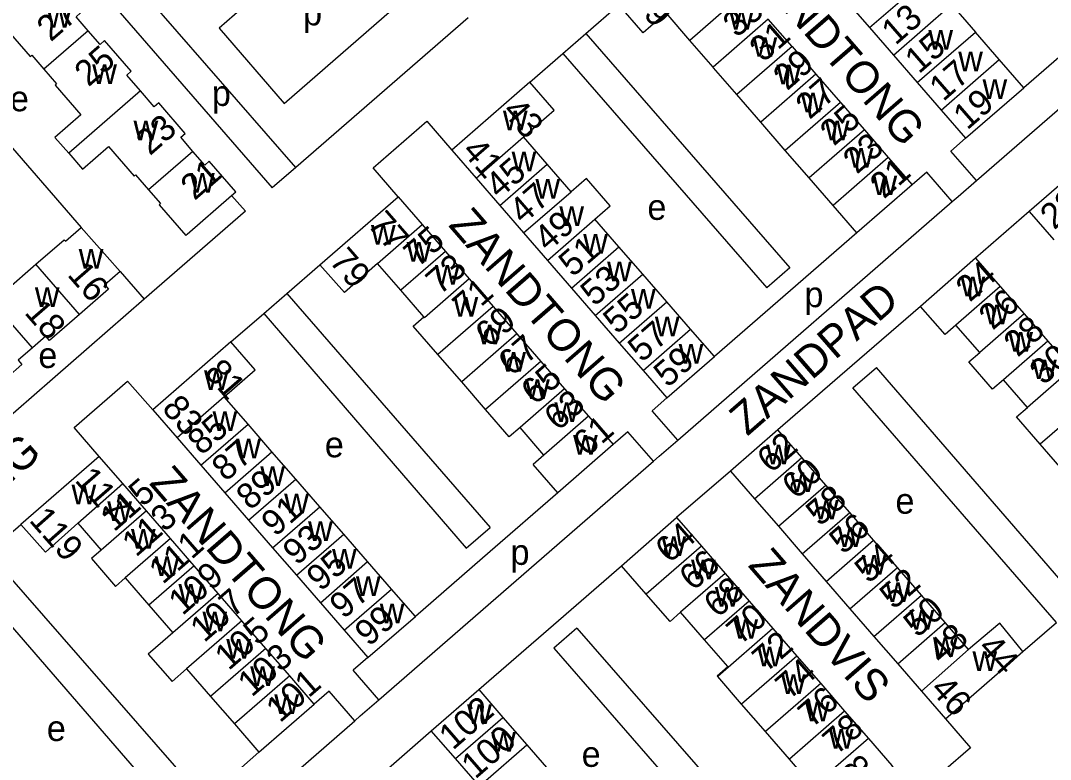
# Model space of a CAD drawing. Extents: x 155854 to 157362, y 383621 to 384685.
# Drawn here: x 156498.5 to 156659.8, y 384332.2 to 384447.9 of the extents above; entities that cross this region are included whole.
import ezdxf

# ---------------------------------------------------------------- set-up
doc = ezdxf.new("R2010")
doc.units = 0
for name, color, linetype in [('BLT_Basislijn', 7, 'Continuous'), ('BLT_Bebouwing', 7, 'Continuous'), ('BLT_Centroide', 7, 'Continuous'), ('BLT_Huisnummer', 7, 'Continuous'), ('BLT_Huisnummer_ tussenligend', 7, 'Continuous'), ('BLT_Huisnummer_reeks', 7, 'Continuous'), ('BLT_Onderverdeling_panden', 7, 'Continuous'), ('BLT_Straatnaam', 7, 'Continuous')]:
    doc.layers.add(name, color=color, linetype=linetype)

msp = doc.modelspace()

# ---------------------------------------------------------------- linework, layer by layer
at = {"layer": 'BLT_Basislijn'}
for p, q in [((156541.64, 384424.92), (156508.8, 384462.59)), ((156505.19, 384459.46), (156537.93, 384421.71)), ((156587.05, 384445.89), (156592.21, 384450.37)), ((156568.62, 384448.35), (156541.64, 384424.92)), ((156667.24, 384447.45), (156655.65, 384437.39)), ((156583.44, 384442.75), (156587.05, 384445.89)), ((156578.29, 384438.28), (156583.44, 384442.75)), ((156583.44, 384442.75), (156615.4, 384406.06)), ((156494.81, 384430.72), (156508, 384415.52)), ((156648.22, 384422.86), (156644.22, 384427.48)), ((156541.64, 384424.92), (156537.93, 384421.71)), ((156644.45, 384419.58), (156640.45, 384424.2)), ((156531.54, 384420.51), (156533.76, 384418.07)), ((156533.76, 384418.07), (156517.89, 384404.28)), ((156656.48, 384418.02), (156648.08, 384410.74)), ((156514.12, 384408.62), (156517.89, 384404.28)), ((156540.2, 384405.2), (156545.38, 384409.7)), ((156536.6, 384402.08), (156540.2, 384405.2)), ((156540.2, 384405.2), (156572.08, 384368.57)), ((156517.89, 384404.28), (156463.21, 384356.78)), ((156531.46, 384397.61), (156536.6, 384402.08)), ((156639.47, 384403.18), (156628.75, 384393.9)), ((156628.75, 384393.9), (156617.13, 384383.84)), ((156664.38, 384356.83), (156632.56, 384393.62)), ((156601.43, 384382.21), (156597.42, 384386.82)), ((156597.65, 384378.93), (156593.64, 384383.54)), ((156609.69, 384377.39), (156601.27, 384370.09)), ((156582.67, 384373.99), (156572.04, 384364.78)), ((156493.41, 384364.56), (156498.56, 384369.04)), ((156572.04, 384364.78), (156560.34, 384354.62)), ((156581.99, 384353.33), (156592.62, 384362.57)), ((156489.82, 384361.43), (156521.66, 384324.72)), ((156655.52, 384349.15), (156660.76, 384353.69)), ((156570.29, 384343.17), (156581.99, 384353.33)), ((156585.66, 384352.81), (156617.61, 384316.2)), ((156552.91, 384348.2), (156550.6, 384346.19)), ((156554.61, 384341.57), (156550.6, 384346.19)), ((156546.82, 384342.91), (156544.51, 384340.9)), ((156550.84, 384338.29), (156546.82, 384342.91)), ((156554.48, 384329.42), (156562.84, 384336.72)), ((156525.13, 384324.03), (156535.85, 384333.36))]:
    msp.add_line(p, q, dxfattribs=at)
for points in [[(156648.22, 384422.86), (156694.85, 384463.4), (156691.17, 384468.24)], [(156587.05, 384445.89), (156619, 384409.22), (156615.4, 384406.06)], [(156557.63, 384420.32), (156553.73, 384424.89), (156562.12, 384432.16), (156566.04, 384427.64)], [(156646.53, 384429.49), (156644.22, 384427.48)], [(156640.45, 384424.2), (156638.14, 384422.19)], [(156644.45, 384419.58), (156645.36, 384420.38), (156648.22, 384422.86)], [(156601.43, 384382.21), (156644.45, 384419.58)], [(156629.49, 384414.69), (156619.12, 384405.68)], [(156619.12, 384405.68), (156607.18, 384395.3)], [(156536.6, 384402.08), (156568.3, 384365.31), (156572.08, 384368.57)], [(156660.76, 384353.69), (156628.85, 384390.4), (156632.56, 384393.62)], [(156510.82, 384379.68), (156506.9, 384384.19), (156515.28, 384391.46), (156519.21, 384386.97)], [(156599.74, 384388.83), (156597.42, 384386.82)], [(156593.64, 384383.54), (156591.32, 384381.53)], [(156597.65, 384378.93), (156598.54, 384379.7), (156601.43, 384382.21)], [(156554.61, 384341.57), (156597.65, 384378.93)], [(156493.41, 384364.56), (156525.42, 384328), (156521.66, 384324.72)], [(156585.66, 384352.81), (156582.05, 384349.68), (156613.96, 384313.03)], [(156550.84, 384338.29), (156551.69, 384339.04), (156554.61, 384341.57)], [(156510.15, 384302.85), (156550.84, 384338.29)], [(156643.36, 384338.6), (156647.29, 384334.04), (156638.86, 384326.74), (156634.97, 384331.3)]]:
    msp.add_lwpolyline(points, dxfattribs=at)
msp.add_lwpolyline([(156539.82, 384434.95), (156559.04, 384451.74), (156548.85, 384463.47), (156529.59, 384446.72)], close=True, dxfattribs=at)
at = {"layer": 'BLT_Bebouwing'}
for p, q in [((156644.32, 384450.43), (156648.06, 384446.12)), ((156619.35, 384443.86), (156615.62, 384448.16)), ((156619.35, 384443.86), (156623.09, 384439.54)), ((156623.09, 384439.54), (156626.93, 384435.11)), ((156578.29, 384438.28), (156566.04, 384427.64)), ((156626.93, 384435.11), (156630.67, 384430.8)), ((156630.67, 384430.8), (156634.42, 384426.49)), ((156566.04, 384427.64), (156569.85, 384423.25)), ((156634.42, 384426.49), (156638.14, 384422.19)), ((156663.92, 384424.49), (156656.48, 384418.02)), ((156569.85, 384423.25), (156573.56, 384418.98)), ((156545.38, 384409.7), (156557.63, 384420.32)), ((156557.63, 384420.32), (156561.4, 384415.98)), ((156573.56, 384418.98), (156577.3, 384414.67)), ((156508, 384415.52), (156514.12, 384408.62)), ((156561.4, 384415.98), (156565.05, 384411.77)), ((156577.3, 384414.67), (156581.05, 384410.36)), ((156565.05, 384411.77), (156568.79, 384407.48)), ((156558.06, 384405.7), (156554.4, 384409.91)), ((156581.05, 384410.36), (156584.79, 384406.05)), ((156648.08, 384410.74), (156639.47, 384403.18)), ((156648.08, 384410.74), (156651.97, 384406.27)), ((156568.79, 384407.48), (156572.53, 384403.17)), ((156584.79, 384406.05), (156588.53, 384401.74)), ((156651.97, 384406.27), (156655.68, 384401.99)), ((156572.53, 384403.17), (156576.26, 384398.87)), ((156655.68, 384401.99), (156659.4, 384397.71)), ((156588.53, 384401.74), (156592.27, 384397.43)), ((156648.74, 384395.96), (156645.02, 384400.24)), ((156576.26, 384398.87), (156580, 384394.56)), ((156531.46, 384397.61), (156519.21, 384386.97)), ((156592.27, 384397.43), (156596.01, 384393.13)), ((156659.4, 384397.71), (156663.17, 384393.38)), ((156580, 384394.56), (156583.73, 384390.27)), ((156599.74, 384388.83), (156607.18, 384395.3)), ((156596.01, 384393.13), (156599.74, 384388.83)), ((156656.22, 384387.34), (156652.46, 384391.67)), ((156583.73, 384390.27), (156587.47, 384385.97)), ((156519.21, 384386.97), (156523.02, 384382.59)), ((156587.47, 384385.97), (156591.32, 384381.53)), ((156576.74, 384384.2), (156575.06, 384382.74)), ((156523.02, 384382.59), (156526.74, 384378.31)), ((156617.13, 384383.84), (156609.69, 384377.39)), ((156510.82, 384379.68), (156498.56, 384369.04)), ((156514.51, 384375.44), (156510.82, 384379.68)), ((156580.48, 384379.9), (156578.8, 384378.44)), ((156526.74, 384378.31), (156530.49, 384374)), ((156609.69, 384377.39), (156613.46, 384373.05)), ((156518.23, 384371.15), (156514.51, 384375.44)), ((156530.49, 384374), (156534.23, 384369.69)), ((156613.46, 384373.05), (156617.2, 384368.74)), ((156521.99, 384366.82), (156518.23, 384371.15)), ((156534.23, 384369.69), (156537.97, 384365.39)), ((156507.49, 384369.21), (156511.15, 384364.99)), ((156617.2, 384368.74), (156620.94, 384364.43)), ((156525.7, 384362.55), (156521.99, 384366.82)), ((156537.97, 384365.39), (156541.72, 384361.07)), ((156620.94, 384364.43), (156624.68, 384360.12)), ((156529.46, 384358.22), (156525.7, 384362.55)), ((156514.91, 384360.67), (156518.62, 384356.4)), ((156541.72, 384361.07), (156545.46, 384356.77)), ((156624.68, 384360.12), (156628.42, 384355.81)), ((156533.18, 384353.93), (156529.46, 384358.22)), ((156545.46, 384356.77), (156549.2, 384352.46)), ((156518.62, 384356.4), (156522.38, 384352.07)), ((156628.42, 384355.81), (156632.17, 384351.5)), ((156536.94, 384349.61), (156533.18, 384353.93)), ((156549.2, 384352.46), (156552.91, 384348.2)), ((156632.17, 384351.5), (156635.9, 384347.19)), ((156540.67, 384345.32), (156536.94, 384349.61)), ((156643.36, 384338.6), (156655.52, 384349.15)), ((156635.9, 384347.19), (156639.62, 384342.9)), ((156544.51, 384340.9), (156540.67, 384345.32)), ((156639.62, 384342.9), (156643.36, 384338.6)), ((156618.93, 384332.28), (156615.18, 384336.61))]:
    msp.add_line(p, q, dxfattribs=at)
for points in [[(156509.11, 384446.34), (156507.2, 384448.53), (156507.88, 384449.12), (156503.74, 384453.9), (156503.07, 384453.3)], [(156599.61, 384449.12), (156596.01, 384445.99), (156592.21, 384450.37)], [(156627.74, 384451.12), (156631.48, 384446.82)], [(156603.33, 384444.83), (156599.61, 384449.12)], [(156490.46, 384446.71), (156492.62, 384444.23), (156495.89, 384447.07), (156500.03, 384442.3), (156500.25, 384442.5), (156502.16, 384440.3)], [(156515.14, 384439.39), (156515.82, 384439.99), (156511.67, 384444.78), (156510.99, 384444.16), (156509.11, 384446.34)], [(156631.48, 384446.82), (156635.22, 384442.52)], [(156651.81, 384441.81), (156648.06, 384446.12)], [(156606.97, 384440.64), (156603.33, 384444.83)], [(156635.22, 384442.52), (156638.96, 384438.21)], [(156610.7, 384436.34), (156607.05, 384440.55), (156606.97, 384440.64)], [(156655.65, 384437.39), (156651.81, 384441.81)], [(156502.16, 384440.3), (156504.16, 384438), (156503.94, 384437.8), (156507.97, 384433.16)], [(156517.29, 384436.91), (156515.14, 384439.39)], [(156577.28, 384429.72), (156582.1, 384433.9), (156578.29, 384438.28)], [(156638.96, 384438.21), (156642.7, 384433.9)], [(156646.53, 384429.49), (156655.65, 384437.39)], [(156525.51, 384427.45), (156523.6, 384429.65), (156524.29, 384430.22), (156520.15, 384435.03), (156519.44, 384434.43), (156517.29, 384436.91)], [(156614.44, 384432.03), (156610.7, 384436.34)], [(156507.97, 384433.16), (156503.89, 384429.62), (156506.04, 384427.14)], [(156642.7, 384433.9), (156646.53, 384429.49)], [(156618.29, 384427.6), (156614.44, 384432.03)], [(156581, 384425.44), (156577.28, 384429.72)], [(156506.04, 384427.14), (156508.19, 384424.66), (156512.27, 384428.19)], [(156512.27, 384428.19), (156516.29, 384423.57), (156516.52, 384423.76), (156518.56, 384421.42)], [(156531.54, 384420.51), (156532.21, 384421.11), (156528.07, 384425.89), (156527.38, 384425.29), (156525.51, 384427.45)], [(156622.03, 384423.29), (156618.29, 384427.6)], [(156584.74, 384421.13), (156581, 384425.44)], [(156588.48, 384416.82), (156590.87, 384418.9), (156587.13, 384423.21), (156584.74, 384421.13)], [(156625.77, 384418.98), (156622.03, 384423.29)], [(156518.56, 384421.42), (156520.42, 384419.28), (156520.2, 384419.08), (156524.37, 384414.28), (156524.6, 384414.48), (156531.54, 384420.51)], [(156638.14, 384422.19), (156629.49, 384414.69)], [(156629.49, 384414.69), (156625.77, 384418.98)], [(156656.48, 384418.02), (156660.35, 384413.57)], [(156592.22, 384412.51), (156588.48, 384416.82)], [(156500.92, 384409.77), (156505.33, 384413.6), (156505.53, 384413.37), (156508, 384415.52)], [(156595.97, 384408.2), (156592.22, 384412.51)], [(156554.4, 384409.91), (156549.23, 384405.36), (156545.38, 384409.7)], [(156494.34, 384403.62), (156496.43, 384405.47), (156496.23, 384405.69), (156500.92, 384409.77)], [(156514.12, 384408.62), (156511.69, 384406.54), (156512.3, 384405.86), (156507.75, 384401.91)], [(156599.71, 384403.9), (156595.97, 384408.2)], [(156561.66, 384401.56), (156558.06, 384405.7)], [(156603.45, 384399.59), (156599.71, 384403.9)], [(156507.75, 384401.91), (156503.05, 384397.83), (156502.46, 384398.52), (156500.37, 384396.68)], [(156645.02, 384400.24), (156643.32, 384398.75), (156639.47, 384403.18)], [(156563.86, 384395.64), (156559.99, 384400.1), (156561.66, 384401.56)], [(156607.18, 384395.3), (156603.45, 384399.59)], [(156530.4, 384389), (156535.27, 384393.22), (156531.46, 384397.61)], [(156500.37, 384396.68), (156498.11, 384394.74), (156498.71, 384394.06), (156494.16, 384390.1)], [(156567.6, 384391.34), (156563.86, 384395.64)], [(156652.46, 384391.67), (156650.75, 384390.19), (156647.03, 384394.48), (156648.74, 384395.96)], [(156571.34, 384387.03), (156567.6, 384391.34)], [(156534.13, 384384.72), (156530.4, 384389)], [(156658.22, 384381.59), (156654.52, 384385.86), (156656.22, 384387.34)], [(156575.06, 384382.74), (156571.34, 384387.03)], [(156537.88, 384380.42), (156534.13, 384384.72)], [(156580.48, 384379.9), (156576.74, 384384.2)], [(156620.89, 384379.51), (156617.13, 384383.84)], [(156591.32, 384381.53), (156582.67, 384373.99)], [(156661.96, 384377.29), (156658.22, 384381.59)], [(156541.62, 384376.11), (156537.88, 384380.42)], [(156624.63, 384375.2), (156620.89, 384379.51)], [(156582.67, 384373.99), (156578.8, 384378.44)], [(156545.37, 384371.81), (156541.62, 384376.11)], [(156628.38, 384370.89), (156624.63, 384375.2)], [(156549.12, 384367.51), (156545.37, 384371.81)], [(156592.62, 384362.57), (156601.27, 384370.09)], [(156601.27, 384370.09), (156605.15, 384365.62)], [(156632.12, 384366.58), (156628.38, 384370.89)], [(156498.56, 384369.04), (156502.4, 384364.7), (156507.49, 384369.21)], [(156552.87, 384363.2), (156549.12, 384367.51)], [(156635.86, 384362.27), (156632.12, 384366.58)], [(156511.15, 384364.99), (156509.62, 384363.67), (156513.36, 384359.33), (156514.91, 384360.67)], [(156605.15, 384365.62), (156608.87, 384361.35)], [(156556.61, 384358.9), (156552.87, 384363.2)], [(156596.5, 384358.11), (156592.62, 384362.57)], [(156639.6, 384357.96), (156635.86, 384362.27)], [(156608.87, 384361.35), (156612.62, 384357.02)], [(156560.34, 384354.62), (156556.61, 384358.9)], [(156601.88, 384355.28), (156600.23, 384353.82), (156596.5, 384358.11)], [(156612.62, 384357.02), (156616.36, 384352.72)], [(156643.34, 384353.65), (156639.6, 384357.96)], [(156605.64, 384350.95), (156601.88, 384355.28)], [(156552.91, 384348.2), (156560.34, 384354.62)], [(156647, 384349.43), (156643.34, 384353.65)], [(156655.52, 384349.15), (156651.89, 384353.56), (156647, 384349.43)], [(156522.38, 384352.07), (156520.79, 384350.69), (156518.51, 384348.73), (156522.24, 384344.43), (156524.52, 384346.41)], [(156616.36, 384352.72), (156620.09, 384348.42)], [(156609.27, 384346.78), (156605.64, 384350.95)], [(156620.09, 384348.42), (156623.83, 384344.12)], [(156524.52, 384346.41), (156528.27, 384342.09)], [(156607.6, 384345.33), (156609.27, 384346.78)], [(156607.7, 384345.21), (156607.6, 384345.33)], [(156611.44, 384340.9), (156607.7, 384345.21)], [(156623.83, 384344.12), (156627.58, 384339.8)], [(156562.84, 384336.72), (156570.29, 384343.17)], [(156570.29, 384343.17), (156574.07, 384338.82)], [(156528.27, 384342.09), (156532, 384337.79)], [(156535.85, 384333.36), (156544.51, 384340.9)], [(156615.18, 384336.61), (156611.44, 384340.9)], [(156627.58, 384339.8), (156631.3, 384335.52)], [(156532, 384337.79), (156535.85, 384333.36)], [(156574.07, 384338.82), (156577.81, 384334.52)], [(156566.63, 384332.36), (156562.84, 384336.72)], [(156577.81, 384334.52), (156581.55, 384330.21)], [(156631.3, 384335.52), (156634.97, 384331.3)], [(156570.37, 384328.06), (156566.63, 384332.36)], [(156622.52, 384328.15), (156618.93, 384332.28)]]:
    msp.add_lwpolyline(points, dxfattribs=at)
at = {"layer": 'BLT_Onderverdeling_panden'}
for p, q in [((156631.48, 384446.82), (156640.59, 384454.73)), ((156611.99, 384452.35), (156603.33, 384444.83)), ((156635.22, 384442.52), (156644.32, 384450.43)), ((156615.62, 384448.16), (156606.97, 384440.64)), ((156509.11, 384446.34), (156502.16, 384440.3)), ((156638.96, 384438.21), (156648.06, 384446.12)), ((156619.35, 384443.86), (156610.7, 384436.34)), ((156642.7, 384433.9), (156651.81, 384441.81)), ((156623.09, 384439.54), (156614.44, 384432.03)), ((156517.29, 384436.91), (156506.04, 384427.14)), ((156626.93, 384435.11), (156618.29, 384427.6)), ((156569.85, 384423.25), (156577.28, 384429.72)), ((156630.67, 384430.8), (156622.03, 384423.29)), ((156525.51, 384427.45), (156518.56, 384421.42)), ((156634.42, 384426.49), (156625.77, 384418.98)), ((156573.56, 384418.98), (156581, 384425.44)), ((156577.3, 384414.67), (156584.74, 384421.13)), ((156581.05, 384410.36), (156588.48, 384416.82)), ((156554.4, 384409.91), (156561.4, 384415.98)), ((156565.05, 384411.77), (156558.06, 384405.7)), ((156584.79, 384406.05), (156592.22, 384412.51)), ((156507.75, 384401.91), (156500.92, 384409.77)), ((156588.53, 384401.74), (156595.97, 384408.2)), ((156651.97, 384406.27), (156645.02, 384400.24)), ((156500.37, 384396.68), (156494.34, 384403.62)), ((156592.27, 384397.43), (156599.71, 384403.9)), ((156572.53, 384403.17), (156563.86, 384395.64)), ((156655.68, 384401.99), (156648.74, 384395.96)), ((156576.26, 384398.87), (156567.6, 384391.34)), ((156596.01, 384393.13), (156603.45, 384399.59)), ((156659.4, 384397.71), (156652.46, 384391.67)), ((156580, 384394.56), (156571.34, 384387.03)), ((156663.17, 384393.38), (156656.22, 384387.34)), ((156530.4, 384389), (156523.02, 384382.59)), ((156583.73, 384390.27), (156576.74, 384384.2)), ((156666.88, 384389.11), (156658.22, 384381.59)), ((156587.47, 384385.97), (156580.48, 384379.9)), ((156526.74, 384378.31), (156534.13, 384384.72)), ((156530.49, 384374), (156537.88, 384380.42)), ((156613.46, 384373.05), (156620.89, 384379.51)), ((156534.23, 384369.69), (156541.62, 384376.11)), ((156507.49, 384369.21), (156514.51, 384375.44)), ((156617.2, 384368.74), (156624.63, 384375.2)), ((156537.97, 384365.39), (156545.37, 384371.81)), ((156518.23, 384371.15), (156511.15, 384364.99)), ((156620.94, 384364.43), (156628.38, 384370.89)), ((156521.99, 384366.82), (156514.91, 384360.67)), ((156541.72, 384361.07), (156549.12, 384367.51)), ((156624.68, 384360.12), (156632.12, 384366.58)), ((156605.15, 384365.62), (156596.5, 384358.11)), ((156545.46, 384356.77), (156552.87, 384363.2)), ((156525.7, 384362.55), (156518.62, 384356.4)), ((156628.42, 384355.81), (156635.86, 384362.27)), ((156608.87, 384361.35), (156601.88, 384355.28)), ((156549.2, 384352.46), (156556.61, 384358.9)), ((156612.62, 384357.02), (156605.64, 384350.95)), ((156632.17, 384351.5), (156639.6, 384357.96)), ((156533.18, 384353.93), (156524.52, 384346.41)), ((156635.9, 384347.19), (156643.34, 384353.65)), ((156616.36, 384352.72), (156607.7, 384345.21)), ((156536.94, 384349.61), (156528.27, 384342.09)), ((156647, 384349.43), (156639.62, 384342.9)), ((156620.09, 384348.42), (156611.44, 384340.9)), ((156540.67, 384345.32), (156532, 384337.79)), ((156623.83, 384344.12), (156615.18, 384336.61)), ((156627.58, 384339.8), (156618.93, 384332.28)), ((156566.63, 384332.36), (156574.07, 384338.82)), ((156570.37, 384328.06), (156577.81, 384334.52))]:
    msp.add_line(p, q, dxfattribs=at)
for points in [[(156568.79, 384407.48), (156561.8, 384401.4), (156561.66, 384401.56)], [(156529.46, 384358.22), (156522.38, 384352.07)], [(156631.3, 384335.52), (156622.65, 384328), (156622.52, 384328.15)]]:
    msp.add_lwpolyline(points, dxfattribs=at)

# ---------------------------------------------------------------- texts
at = {"layer": 'BLT_Centroide'}
for s, p in [('p', (156542.76, 384447.18)), ('w', (156502.61, 384446.8)), ('w', (156609.48, 384446.5)), ('w', (156640.7, 384443.37)), ('w', (156613.16, 384442.25)), ('w', (156645.38, 384440)), ('w', (156509.73, 384437.98)), ('w', (156616.9, 384437.94)), ('p', (156528.47, 384434.56)), ('w', (156649.18, 384435.66)), ('e', (156496.83, 384433.72)), ('w', (156620.69, 384433.56)), ('w', (156574.06, 384430.75)), ('w', (156516.2, 384429.16)), ('w', (156624.48, 384429.19)), ('w', (156628.23, 384424.91)), ('w', (156575.42, 384424.34)), ('w', (156525.05, 384420.97)), ('w', (156579.15, 384420.06)), ('w', (156631.96, 384420.59)), ('e', (156596.69, 384416.72)), ('w', (156582.9, 384415.75)), ('w', (156553.39, 384412.84)), ('w', (156558.97, 384410.19)), ('w', (156586.63, 384411.44)), ('w', (156507.62, 384409.08)), ('w', (156590.38, 384407.12)), ('w', (156563.42, 384406.59)), ('w', (156645.73, 384404.75)), ('w', (156500.75, 384403.09)), ('w', (156594.12, 384402.81)), ('p', (156621.29, 384403.05)), ('w', (156566.32, 384401.56)), ('w', (156649.49, 384400.38)), ('w', (156570.06, 384397.25)), ('w', (156597.86, 384398.5)), ('w', (156653.22, 384396.09)), ('w', (156601.59, 384394.22)), ('e', (156501.29, 384393.53)), ('w', (156573.8, 384392.94)), ('w', (156656.95, 384391.78)), ('w', (156527.24, 384390.09)), ('w', (156577.53, 384388.66)), ('w', (156582.11, 384385.09)), ('w', (156528.58, 384383.66)), ('w', (156532.3, 384379.38)), ('e', (156546.16, 384379.54)), ('w', (156585.05, 384379.97)), ('w', (156615.29, 384378.44)), ('w', (156536.05, 384375.06)), ('w', (156619.04, 384374.12)), ('w', (156506.49, 384372.19)), ('w', (156539.8, 384370.75)), ('w', (156622.79, 384369.81)), ('e', (156635.54, 384370.71)), ('w', (156512.09, 384369.56)), ('w', (156515.8, 384365.25)), ('w', (156543.54, 384366.44)), ('w', (156626.52, 384365.5)), ('w', (156598.89, 384364.09)), ('w', (156547.29, 384362.12)), ('p', (156575.25, 384362.7)), ('w', (156519.52, 384360.94)), ('w', (156603.52, 384360.44)), ('w', (156630.27, 384361.19)), ('w', (156551.03, 384357.84)), ('w', (156634.01, 384356.88)), ('w', (156523.24, 384356.62)), ('w', (156607.25, 384356.16)), ('w', (156526.99, 384352.31)), ('w', (156554.77, 384353.56)), ('w', (156637.75, 384352.56)), ('w', (156610.16, 384351.12)), ('w', (156530.73, 384348)), ('w', (156641.42, 384348.28)), ('w', (156613.9, 384346.81)), ('w', (156647.6, 384346.09)), ('w', (156534.48, 384343.72)), ('w', (156617.63, 384342.5)), ('w', (156538.25, 384339.34)), ('w', (156568.45, 384337.78)), ('w', (156621.38, 384338.19)), ('e', (156502.62, 384335.12)), ('w', (156572.22, 384333.44)), ('w', (156625.12, 384333.91)), ('e', (156586.39, 384331.07))]:
    msp.add_text(s, height=4, dxfattribs=at).set_placement(p)
at = {"layer": 'BLT_Huisnummer'}
for s, rotation, p in [('27', 40.9815, (156503.23, 384444.49)), ('33', 40.9795, (156610.7, 384445.12)), ('15', 40.9786, (156639.21, 384439.47)), ('25', 40.9815, (156509.14, 384437.44)), ('29', 40.9795, (156618.57, 384436.85)), ('19', 40.9786, (156646.78, 384430.68)), ('25', 40.9795, (156625.9, 384428.17)), ('23', 40.9815, (156518.76, 384426.67)), ('21', 40.9795, (156633.73, 384419.89)), ('21', 40.9815, (156525.76, 384419.65)), ('47', 40.9795, (156577.22, 384415.91)), ('22', 41.2107, (156660.41, 384415.05)), ('51', 40.9795, (156584.98, 384407.64)), ('16', 310.985, (156505.7, 384408.07)), ('73', 40.9795, (156564.18, 384404.84)), ('24', 40.9816, (156647.18, 384403.74)), ('55', 40.9795, (156591.95, 384398.68)), ('69', 40.9795, (156571.9, 384396.58)), ('28', 40.9816, (156654.68, 384395.11)), ('59', 40.9795, (156599.86, 384390.33)), ('65', 40.9795, (156579.09, 384387.6)), ('61', 40.9795, (156587.25, 384379.52)), ('62', 40.9799, (156616.05, 384376.92)), ('87', 40.9795, (156530.64, 384375.61)), ('58', 40.9799, (156623.7, 384368.61)), ('91', 40.9795, (156538.4, 384366.98)), ('113', 40.9795, (156516.58, 384363.81)), ('64', 40.9816, (156600.11, 384362.83)), ('95', 40.9795, (156545.49, 384358.42)), ('54', 40.9799, (156631.34, 384359.65)), ('109', 40.9795, (156523.86, 384354.65)), ('68', 40.9816, (156607.7, 384354.28)), ('50', 40.9799, (156638.99, 384351.18)), ('99', 40.9795, (156553.05, 384349.79)), ('105', 40.9795, (156531.1, 384346.04)), ('72', 40.9816, (156615.3, 384345.76)), ('101', 40.9795, (156539.13, 384337.86)), ('76', 40.9816, (156622.47, 384337.07)), ('102', 40.9816, (156566.22, 384333.58))]:
    msp.add_text(s, height=4, rotation=rotation, dxfattribs=at).set_placement(p)
at = {"layer": 'BLT_Huisnummer_ tussenligend'}
for s, rotation, p in [('13', 40.9786, (156635.55, 384443.95)), ('31', 40.9795, (156614.87, 384441.27)), ('17', 40.9786, (156643.03, 384435.15)), ('27', 40.9795, (156622.09, 384432.33)), ('23', 40.9795, (156629.5, 384423.77)), ('45', 40.9795, (156573.49, 384419.89)), ('49', 40.9795, (156581.11, 384411.6)), ('75', 40.9795, (156560.71, 384409.15)), ('53', 40.9795, (156588.4, 384403.05)), ('71', 40.9795, (156568.37, 384401.04)), ('26', 40.9816, (156650.77, 384399.34)), ('18', 310.985, (156498.98, 384402.13)), ('57', 40.9795, (156595.82, 384394.27)), ('67', 40.9795, (156575.5, 384392.12)), ('30', 40.9816, (156658.74, 384390.71)), ('63', 40.9795, (156582.7, 384383.54)), ('85', 40.9795, (156526.85, 384379.72)), ('60', 40.9799, (156619.95, 384372.84)), ('115', 40.9795, (156513.14, 384367.75)), ('89', 40.9795, (156534.47, 384371.11)), ('56', 40.9799, (156627.36, 384364.21)), ('93', 40.9795, (156541.77, 384362.48)), ('111', 40.9795, (156520.79, 384359.54)), ('66', 40.9816, (156603.86, 384358.5)), ('52', 40.9799, (156635.26, 384355.59)), ('97', 40.9795, (156549.1, 384354.09)), ('107', 40.9795, (156527.26, 384350.42)), ('70', 40.9816, (156611.27, 384350.07)), ('48', 40.9799, (156642.74, 384346.95)), ('103', 40.9795, (156534.71, 384341.88)), ('74', 40.9816, (156618.94, 384341.5)), ('78', 40.9816, (156626.33, 384332.84)), ('100', 40.9816, (156569.73, 384329.04))]:
    msp.add_text(s, height=4, rotation=rotation, dxfattribs=at).set_placement(p)
at = {"layer": 'BLT_Huisnummer_reeks'}
for s, rotation, p in [('39', 309.5726, (156594.05, 384451.17)), ('43', 310.9641, (156573.8, 384433.64)), ('41', 310.9745, (156567.49, 384427.4)), ('77', 310.9745, (156552.68, 384415.92)), ('79', 310.9745, (156546.71, 384410.18)), ('81', 310.9745, (156527.14, 384392.75)), ('83', 310.9745, (156520.5, 384387.12)), ('117', 310.9827, (156506.87, 384375.88)), ('119', 311.4586, (156499.71, 384369.61)), ('44', 312.0599, (156648.29, 384349.58)), ('46', 312.0599, (156640.84, 384343.1)), ('80', 312.0599, (156626.82, 384330.71))]:
    msp.add_text(s, height=4, rotation=rotation, dxfattribs=at).set_placement(p)
at = {"layer": 'BLT_Straatnaam'}
for s, rotation, p in [('ZANDTONG', 310.9823, (156612.18, 384456.2)), ('ZANDTONG', 310.9823, (156565.4, 384415.83)), ('ZANDPAD', 40.9819, (156612.33, 384382.76)), ('ZANDTONG', 40.9818, (156473.73, 384355.33)), ('ZANDTONG', 310.9823, (156518.53, 384375.43)), ('ZANDVIS', 310.9816, (156612.32, 384362.56))]:
    msp.add_text(s, height=5, rotation=rotation, dxfattribs=at).set_placement(p)

doc.saveas('drawing.dxf')
